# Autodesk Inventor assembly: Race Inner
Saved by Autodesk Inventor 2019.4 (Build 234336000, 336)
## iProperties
Created: 2020-05
Part Number: Race Inner
Document SubType Name: Assembly
Designer: Administrator
Title: Race Inner
Author: Administrator
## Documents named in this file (3)
- c:\worker\convert-fusion-r04\tmp\job-1\2948\output\files\178587fc-8fac-4631-8e4c-cfe484ac4050\Race Inner.iam
- c:\worker\convert-fusion-r04\tmp\job-1\2948\output\files\178587fc-8fac-4631-8e4c-cfe484ac4050\Race Inner Bottom.ipt
- c:\worker\convert-fusion-r04\tmp\job-1\2948\output\files\178587fc-8fac-4631-8e4c-cfe484ac4050\Race Inner Top.ipt
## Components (2 placed, 2 different names)
1. Race Inner Bottom:1
2. Race Inner Top:1
